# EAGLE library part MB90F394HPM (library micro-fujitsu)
F2MC-16LX MB90390 Series; 16-bit Proprietary Microcontroller CMOS MB90F394H/V390 ds90390-ds07-13722-1e.pdf http://www.fme.gsdc.de
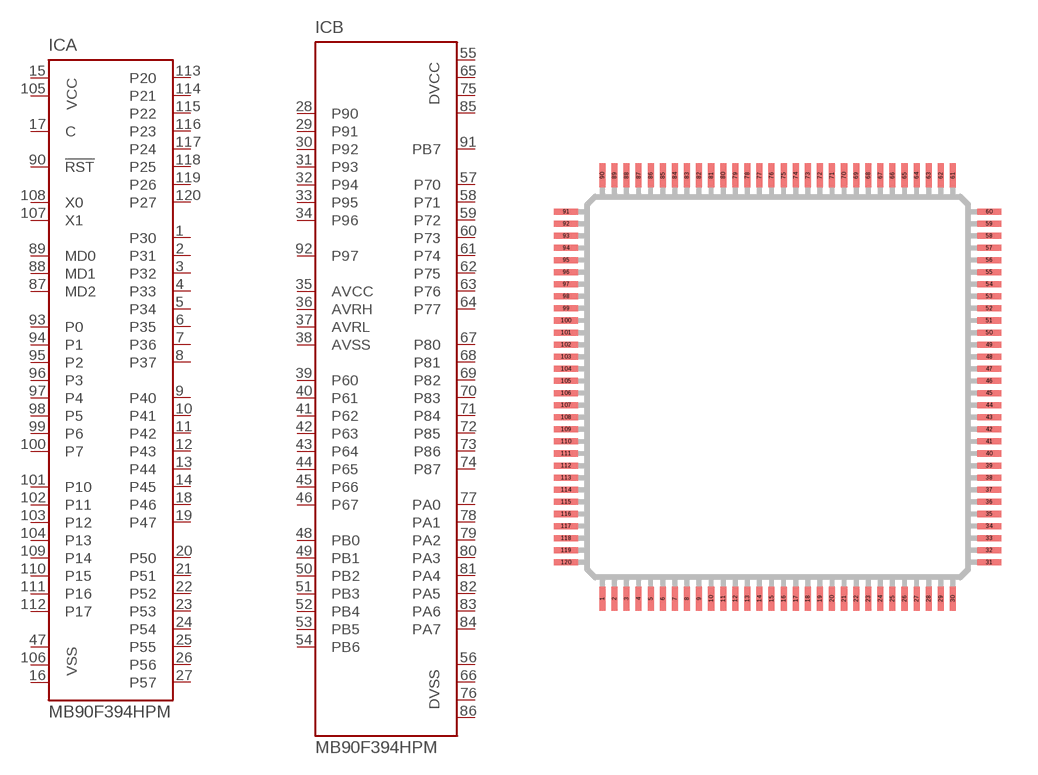
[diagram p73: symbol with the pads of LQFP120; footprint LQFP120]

Designator prefix IC; gates A=MB90390 B=MB90390-2

## MB90F394HPMT (OC_FARNELL: unknown; OC_NEWARK: unknown)  [LQFP120]
1  A:P30
2  A:P31
3  A:P32
4  A:P33
5  A:P34
6  A:P35
7  A:P36
8  A:P37
9  A:P40
10  A:P41
11  A:P42
12  A:P43
13  A:P44
14  A:P45
15  A:VCC  pwr
16  A:VSS  pwr
17  A:C  in
18  A:P46
19  A:P47
20  A:P50
21  A:P51
22  A:P52
23  A:P53
24  A:P54
25  A:P55
26  A:P56
27  A:P57
28  B:P90
29  B:P91
30  B:P92
31  B:P93
32  B:P94
33  B:P95
34  B:P96
35  B:AVCC  pwr
36  B:AVRH  in
37  B:AVRL  in
38  B:AVSS  pwr
39  B:P60
40  B:P61
41  B:P62
42  B:P63
43  B:P64
44  B:P65
45  B:P66
46  B:P67
47  A:VSS2  pwr
48  B:PB0
49  B:PB1
50  B:PB2
51  B:PB3
52  B:PB4
53  B:PB5
54  B:PB6
55  B:DVCC  pwr
56  B:DVSS  pwr
57  B:P70
58  B:P71
59  B:P72
60  B:P73
61  B:P74
62  B:P75
63  B:P76
64  B:P77
65  B:DVCC  pwr
66  B:DVSS  pwr
67  B:P80
68  B:P81
69  B:P82
70  B:P83
71  B:P84
72  B:P85
73  B:P86
74  B:P87
75  B:DVCC  pwr
76  B:DVSS  pwr
77  B:PA0
78  B:PA1
79  B:PA2
80  B:PA3
81  B:PA4
82  B:PA5
83  B:PA6
84  B:PA7
85  B:DVCC  pwr
86  B:DVSS  in
87  A:MD2  in
88  A:MD1  in
89  A:MD0  in
90  A:!RST  in
91  B:PB7
92  B:P97
93  A:P0
94  A:P1
95  A:P2
96  A:P3
97  A:P4
98  A:P5
99  A:P6
100  A:P7
101  A:P10
102  A:P11
103  A:P12
104  A:P13
105  A:VCC1  pwr
106  A:VSS1  pwr
107  A:X1  out
108  A:X0  in
109  A:P14
110  A:P15
111  A:P16
112  A:P17
113  A:P20
114  A:P21
115  A:P22
116  A:P23
117  A:P24
118  A:P25
119  A:P26
120  A:P27

## Footprint LQFP120 (pad centres in mm)
120-pin Plastic LQFP (FPT-120P-M21) ds90390-ds07-13722-1e.pdf http://www.fme.gsdc.de
smd 0.25 x 1: 1 -7.25,-8.75; 2 -6.75,-8.75; 3 -6.25,-8.75; 4 -5.75,-8.75; 5 -5.25,-8.75; 6 -4.75,-8.75; 7 -4.25,-8.75; 8 -3.75,-8.75; 9 -3.25,-8.75; 10 -2.75,-8.75; 11 -2.25,-8.75; 12 -1.75,-8.75; 13 -1.25,-8.75; 14 -0.75,-8.75; 15 -0.25,-8.75; 16 0.25,-8.75; 17 0.75,-8.75; 18 1.25,-8.75; 19 1.75,-8.75; 20 2.25,-8.75; 21 2.75,-8.75; 22 3.25,-8.75; 23 3.75,-8.75; 24 4.25,-8.75; 25 4.75,-8.75; 26 5.25,-8.75; 27 5.75,-8.75; 28 6.25,-8.75; 29 6.75,-8.75; 30 7.25,-8.75; 61 7.25,8.75; 62 6.75,8.75; 63 6.25,8.75; 64 5.75,8.75; 65 5.25,8.75; 66 4.75,8.75; 67 4.25,8.75; 68 3.75,8.75; 69 3.25,8.75; 70 2.75,8.75; 71 2.25,8.75; 72 1.75,8.75; 73 1.25,8.75; 74 0.75,8.75; 75 0.25,8.75; 76 -0.25,8.75; 77 -0.75,8.75; 78 -1.25,8.75; 79 -1.75,8.75; 80 -2.25,8.75; 81 -2.75,8.75; 82 -3.25,8.75; 83 -3.75,8.75; 84 -4.25,8.75; 85 -4.75,8.75; 86 -5.25,8.75; 87 -5.75,8.75; 88 -6.25,8.75; 89 -6.75,8.75; 90 -7.25,8.75
smd 1 x 0.25: 31 8.75,-7.25; 32 8.75,-6.75; 33 8.75,-6.25; 34 8.75,-5.75; 35 8.75,-5.25; 36 8.75,-4.75; 37 8.75,-4.25; 38 8.75,-3.75; 39 8.75,-3.25; 40 8.75,-2.75; 41 8.75,-2.25; 42 8.75,-1.75; 43 8.75,-1.25; 44 8.75,-0.75; 45 8.75,-0.25; 46 8.75,0.25; 47 8.75,0.75; 48 8.75,1.25; 49 8.75,1.75; 50 8.75,2.25; 51 8.75,2.75; 52 8.75,3.25; 53 8.75,3.75; 54 8.75,4.25; 55 8.75,4.75; 56 8.75,5.25; 57 8.75,5.75; 58 8.75,6.25; 59 8.75,6.75; 60 8.75,7.25; 91 -8.75,7.25; 92 -8.75,6.75; 93 -8.75,6.25; 94 -8.75,5.75; 95 -8.75,5.25; 96 -8.75,4.75; 97 -8.75,4.25; 98 -8.75,3.75; 99 -8.75,3.25; 100 -8.75,2.75; 101 -8.75,2.25; 102 -8.75,1.75; 103 -8.75,1.25; 104 -8.75,0.75; 105 -8.75,0.25; 106 -8.75,-0.25; 107 -8.75,-0.75; 108 -8.75,-1.25; 109 -8.75,-1.75; 110 -8.75,-2.25; 111 -8.75,-2.75; 112 -8.75,-3.25; 113 -8.75,-3.75; 114 -8.75,-4.25; 115 -8.75,-4.75; 116 -8.75,-5.25; 117 -8.75,-5.75; 118 -8.75,-6.25; 119 -8.75,-6.75; 120 -8.75,-7.25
